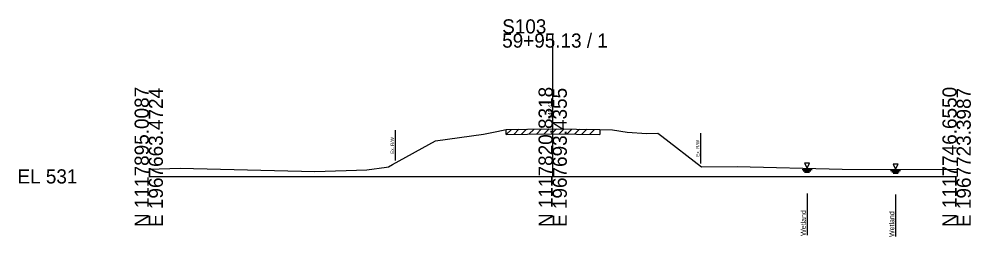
# Model space of a CAD drawing. Extents: x -26 to 163, y -10 to 24018.
# Drawn here: x -25.7 to 162.8, y 9488 to 9531.1 of the extents above; entities that cross this region are included whole.
import ezdxf

# ---------------------------------------------------------------- set-up
doc = ezdxf.new("R2010")
doc.units = 0
for name, color, linetype in [('RD_GPK_XS_Cell', 7, 'Continuous'), ('RD_XS_ExGround', 7, 'Continuous'), ('RD_XS_ExPaveRet', 7, 'Continuous'), ('RD_XS_ExRW', 7, 'Continuous'), ('RD_XS_EXWetland', 7, 'Continuous'), ('RD_XS_TX_Elev_EX', 7, 'Continuous')]:
    doc.layers.add(name, color=color, linetype=linetype)

msp = doc.modelspace()

# ---------------------------------------------------------------- linework, layer by layer
at = {"layer": 'RD_GPK_XS_Cell'}
for p, q in [((80, 9500), (80, 9528.23)), ((0, 9500), (80, 9500)), ((80, 9500), (160, 9500))]:
    msp.add_line(p, q, dxfattribs=at)
at = {"layer": 'RD_XS_ExGround'}
msp.add_lwpolyline([(0, 9501.46), (6.2, 9501.6), (32.88, 9501), (43.17, 9501.32), (47.06, 9501.84), (47.47, 9501.9), (48.27, 9502.33), (56.8, 9507.05), (59.19, 9507.34), (66.3, 9508.34), (68.91, 9508.85), (70.79, 9509.27), (75.03, 9509.34), (79.82, 9509.41), (84.72, 9509.33), (89.35, 9509.26), (91.83, 9509.23), (94.74, 9508.75), (98.65, 9508.49), (100.8, 9508.53), (101.62, 9507.97), (109.48, 9501.91), (116.51, 9501.97), (137.33, 9501.45), (160, 9501.34)], dxfattribs=at)
at = {"layer": 'RD_XS_ExPaveRet'}
for p, q in [((70.79, 9508.27), (71.81, 9509.29)), ((70.79, 9508.27), (70.79, 9509.27)), ((70.79, 9508.27), (75.03, 9508.34)), ((72.29, 9508.29), (73.31, 9509.31)), ((73.79, 9508.32), (74.81, 9509.33)), ((75.03, 9508.34), (79.82, 9508.41)), ((75.29, 9508.34), (76.31, 9509.36)), ((76.79, 9508.36), (77.81, 9509.38)), ((78.29, 9508.39), (79.31, 9509.4)), ((79.79, 9508.41), (80.78, 9509.4)), ((79.82, 9508.41), (84.72, 9508.33)), ((81.29, 9508.39), (82.28, 9509.37)), ((82.79, 9508.36), (83.78, 9509.35)), ((84.29, 9508.34), (85.28, 9509.32)), ((84.72, 9508.33), (89.35, 9508.26)), ((85.79, 9508.32), (86.78, 9509.3)), ((87.29, 9508.29), (88.28, 9509.28)), ((89.35, 9509.26), (89.35, 9508.26))]:
    msp.add_line(p, q, dxfattribs=at)
at = {"layer": 'RD_XS_ExRW'}
for p, q in [((48.8, 9509.13), (48.8, 9503.13)), ((109.3, 9508.55), (109.3, 9502.55))]:
    msp.add_line(p, q, dxfattribs=at)
at = {"layer": 'RD_XS_EXWetland'}
for p, q in [((129.89, 9502.62), (130.39, 9501.62)), ((130.89, 9502.62), (129.89, 9502.62)), ((130.39, 9501.62), (130.89, 9502.62)), ((147.4, 9502.4), (147.9, 9501.4)), ((148.4, 9502.4), (147.4, 9502.4)), ((147.9, 9501.4), (148.4, 9502.4)), ((129.39, 9501.37), (131.39, 9501.37)), ((129.64, 9501.12), (131.14, 9501.12)), ((129.89, 9500.87), (130.89, 9500.87)), ((146.9, 9501.15), (148.9, 9501.15)), ((147.15, 9500.9), (148.65, 9500.9)), ((147.4, 9500.65), (148.4, 9500.65)), ((130.39, 9496.62), (130.39, 9488.37)), ((147.9, 9496.4), (147.9, 9488.15))]:
    msp.add_line(p, q, dxfattribs=at)

# ---------------------------------------------------------------- texts
at = {"layer": 'RD_GPK_XS_Cell'}
for s, p in [('S103', (70, 9528.23)), ('59+95.13 / 1', (70, 9525.43)), ('EL 531', (-26, 9498.6))]:
    msp.add_text(s, height=2.8, dxfattribs=at).set_placement(p)
for s, p in [('N 1117895.0087', (0, 9490)), ('E 1967663.4724', (2.8, 9490)), ('N 1117820.8318', (80, 9490)), ('E 1967693.4355', (82.8, 9490)), ('N 1117746.6550', (160, 9490)), ('E 1967723.3987', (162.8, 9490))]:
    msp.add_text(s, height=2.8, rotation=90, dxfattribs=at).set_placement(p)
at = {"layer": 'RD_XS_ExRW'}
for p in [(48.55, 9504.47), (109.05, 9503.9)]:
    msp.add_text('Ex. R/W ', height=0.65, rotation=90, dxfattribs=at).set_placement(p)
at = {"layer": 'RD_XS_EXWetland'}
for p in [(130.14, 9488.26), (147.65, 9488.04)]:
    msp.add_text('Wetland ', height=1, rotation=90, dxfattribs=at).set_placement(p)
at = {"layer": 'RD_XS_TX_Elev_EX'}
msp.add_text('540.41', height=0.8, rotation=90, dxfattribs=at).set_placement((79.9, 9511.41))

doc.saveas('drawing.dxf')
